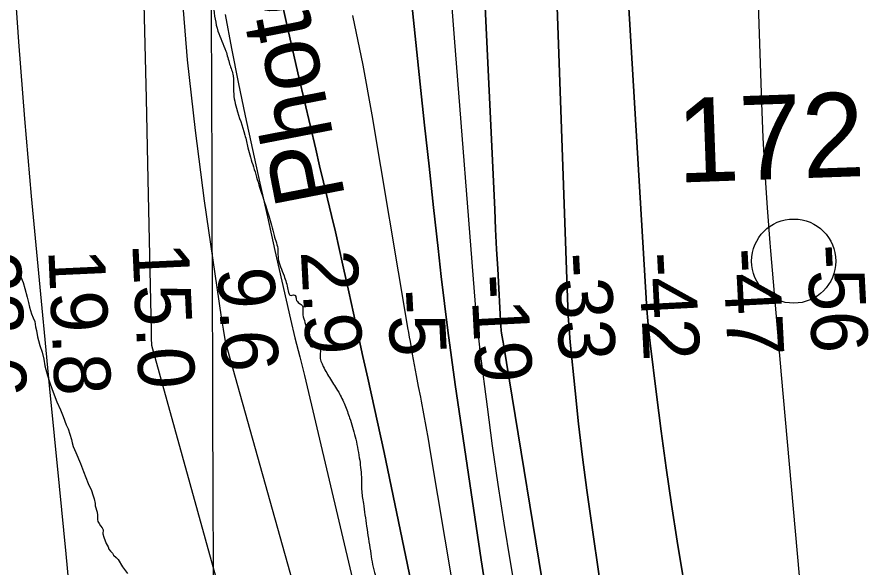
# Model space of a CAD drawing. Extents: x 3392644 to 3430565, y 576657 to 602123.
# Drawn here: x 3401788 to 3402811, y 590281 to 590935 of the extents above; entities that cross this region are included whole.
import ezdxf

# ---------------------------------------------------------------- set-up
doc = ezdxf.new("R2010")
doc.units = 0
for name, color, linetype in [('V-GRID-MAJR', 7, 'Continuous'), ('V-RIVR-EDGE', 7, 'Continuous'), ('V-RIVR-IDEN', 7, 'Continuous'), ('V-RIVR-MILE', 7, 'Continuous'), ('V-RIVR-RANG', 7, 'Continuous'), ('V-SITE-VEGE', 7, 'Continuous'), ('V-TOPO-DPTH', 7, 'Continuous'), ('V-TOPO-MAJR', 7, 'Continuous'), ('V-TOPO-MINR', 7, 'Continuous'), ('V-TOPO-WATR', 7, 'Continuous')]:
    doc.layers.add(name, color=color, linetype=linetype)

msp = doc.modelspace()

# ---------------------------------------------------------------- linework, layer by layer
at = {"layer": 'V-GRID-MAJR'}
msp.add_spline([(3402048.6720000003, 582063.4890000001), (3402028.4020000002, 588122.6730000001), (3402008.125, 594183.791), (3401987.849, 600244.93), (3401987.843, 600246.845)], degree=3, dxfattribs=at)
at = {"layer": 'V-RIVR-EDGE'}
for points in [[(3401987.9213314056, 591815.3849305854), (3401986.374240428, 591794.2696732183), (3401984.9403506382, 591784.4067082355), (3401983.8640619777, 591776.657111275), (3401978.9012120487, 591764.6886201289), (3401977.1132064, 591754.1217800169), (3401973.567691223, 591745.3211626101), (3401971.4360255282, 591738.2789260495), (3401969.6454059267, 591726.6549662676), (3401969.2668931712, 591716.0846408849), (3401969.2590513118, 591712.9132818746), (3401968.1827626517, 591705.1636849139), (3401965.688267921, 591693.8938409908), (3401962.838786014, 591681.5677487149), (3401961.7755671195, 591679.1037501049), (3401961.420579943, 591678.0475017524), (3401960.3608463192, 591676.9929960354), (3401957.895105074, 591677.351468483), (3401951.2113409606, 591681.9488754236), (3401944.5240915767, 591685.1367894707), (3401941.7051057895, 591685.1437600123), (3401942.052251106, 591683.0286493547), (3401946.620033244, 591677.7317238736), (3401950.8371847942, 591673.1404161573), (3401957.5113644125, 591664.6669037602), (3401962.0843744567, 591661.4842176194), (3401967.720603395, 591660.7655300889), (3401970.1819880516, 591658.6451915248), (3401967.3473185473, 591652.309444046), (3401963.8201010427, 591650.9086643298), (3401963.465113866, 591649.8524159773), (3401963.457272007, 591646.681056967), (3401964.845853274, 591638.2206143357), (3401962.369656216, 591634.3506081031), (3401959.531501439, 591626.6053677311), (3401959.5245308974, 591623.7863819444), (3401959.849893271, 591612.8619407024), (3401959.83508087, 591606.8715959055), (3401960.503231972, 591592.0701778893), (3401959.085897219, 591588.9023041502), (3401954.8548045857, 591587.8556402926), (3401949.5665922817, 591586.8115903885), (3401948.5025020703, 591583.995218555), (3401948.4842043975, 591576.5953808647), (3401949.8928259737, 591576.2395223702), (3401955.530797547, 591576.2255812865), (3401957.2883070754, 591574.4593585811), (3401957.27872258, 591570.5832531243), (3401962.5102992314, 591548.7230435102), (3401966.3280264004, 591525.1044530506), (3401969.443621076, 591502.5447248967), (3401975.3869147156, 591483.5017584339), (3401978.862724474, 591464.112517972), (3401980.895059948, 591430.9842070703), (3401982.5889632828, 591403.4947390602), (3401980.7844025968, 591386.2328077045), (3401978.650122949, 591378.1334514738), (3401977.190093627, 591357.6992897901), (3401976.752331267, 591323.1675852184), (3401976.330252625, 591294.9785986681), (3401975.6089511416, 591288.2852500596), (3401977.3481629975, 591279.1191896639), (3401981.890676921, 591263.6034407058), (3401986.4410327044, 591251.2590507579), (3401992.0302104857, 591231.5122091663), (3401995.162360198, 591215.6475722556), (3402000.3695399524, 591183.9209123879), (3402003.4642230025, 591152.904226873), (3402003.0177474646, 591114.8487900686), (3402003.616193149, 591071.8575141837), (3402003.1975997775, 591045.0780205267), (3402005.2621740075, 591024.987518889), (3402008.735369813, 591004.5411587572), (3402015.3502998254, 590972.1062671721), (3402020.9281504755, 590947.7785736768), (3402026.4946739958, 590918.8700282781), (3402035.9503727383, 590895.2374967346), (3402040.4928866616, 590879.7217477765), (3402044.68738395, 590865.968736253), (3402045.0005478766, 590850.1110698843), (3402048.467644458, 590827.198097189), (3402058.6080493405, 590795.4592388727), (3402062.094314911, 590780.2984770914), (3402068.73364182, 590757.7300357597), (3402076.0733585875, 590733.3979856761), (3402090.056758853, 590688.2593603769), (3402093.19849306, 590676.2708289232), (3402097.73490776, 590658.2884674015), (3402098.0637554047, 590648.7735190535), (3402100.858344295, 590638.9000982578), (3402105.0606834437, 590628.3184457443)], [(3402105.0606834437, 590628.3184457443), (3402109.601454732, 590612.09795034), (3402110.2974880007, 590608.5724754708), (3402112.403014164, 590605.0435153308), (3402117.337110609, 590605.383690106), (3402118.3924876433, 590604.6763297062), (3402119.439151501, 590600.4452370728), (3402123.3030585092, 590595.502427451), (3402126.819820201, 590592.6747284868), (3402127.1582523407, 590587.0358855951), (3402131.3405511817, 590568.3496489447), (3402134.468344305, 590550.7231459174), (3402136.9192731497, 590544.3743286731), (3402142.908746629, 590544.0071430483), (3402147.13286872, 590542.2348211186), (3402147.8167035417, 590533.7761211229), (3402151.659698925, 590520.3763541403), (3402160.0800609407, 590505.555767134), (3402169.908173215, 590490.0269484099)], [(3402169.908173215, 590490.0269484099), (3402177.270544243, 590474.8566021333), (3402182.8701778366, 590459.3382392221), (3402189.5103760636, 590437.122171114), (3402194.3817376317, 590412.0914738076), (3402196.7917145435, 590389.1811150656), (3402197.107492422, 590374.3805683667), (3402199.180779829, 590357.8137989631), (3402202.9897938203, 590330.6714762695), (3402207.4983263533, 590301.4131716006), (3402212.367945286, 590275.6777278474), (3402219.3692299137, 590256.9845206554), (3402224.268473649, 590243.2297664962), (3402225.6457277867, 590230.1884719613), (3402225.599547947, 590211.5126911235)]]:
    msp.add_spline(points, degree=3, dxfattribs=at)
at = {"layer": 'V-RIVR-MILE'}
msp.add_circle((3402710.0330000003, 590645.697), 50.00000000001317, dxfattribs=at)
at = {"layer": 'V-SITE-VEGE'}
for points in [[(3401787.631, 590639.961), (3401792.1380000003, 590627.808), (3401795.307, 590620.3250000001), (3401797.549, 590613.317), (3401800.218, 590603.0480000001), (3401801.535, 590596.517), (3401802.864, 590590.916), (3401805.096, 590582.978), (3401807.365, 590578.2980000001), (3401809.178, 590574.087), (3401810.0300000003, 590567.562), (3401811.375, 590563.358), (3401812.217, 590555.901), (3401813.556, 590551.232), (3401815.35, 590545.626), (3401818.048, 590537.682), (3401819.807, 590529.283), (3401821.107, 590521.357), (3401824.224, 590509.686), (3401826.463, 590502.213), (3401829.613, 590493.333), (3401835.482, 590478.37), (3401839.56, 590469.015), (3401842.722, 590461.064), (3401846.326, 590451.248), (3401848.596, 590446.568), (3401852.632, 590433.955), (3401853.5130000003, 590429.756), (3401854.858, 590425.552), (3401858.0330000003, 590418.533), (3401863.46, 590405.438), (3401867.0640000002, 590395.622), (3401872.4790000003, 590381.596), (3401876.5670000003, 590373.17), (3401877.9, 590368.034), (3401879.707, 590363.36), (3401881.036, 590357.759), (3401881.001, 590354.968), (3401883.24, 590347.4940000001), (3401883.659, 590343.767), (3401883.598, 590338.647), (3401884.034, 590336.316), (3401885.4020000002, 590333.974), (3401887.231, 590331.16), (3401889.0640000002, 590328.811), (3401890.432, 590326.468), (3401889.912, 590321.819), (3401891.253, 590317.6140000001), (3401893.9590000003, 590310.137), (3401896.24, 590306.387), (3401897.137, 590303.583), (3401898.97, 590301.234)], [(3401898.97, 590301.234), (3401901.268, 590298.879), (3401902.636, 590296.536), (3401905.86, 590293.706), (3401908.16, 590291.351), (3401913.171, 590282.452), (3401919.125, 590274.4670000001)]]:
    msp.add_lwpolyline(points, dxfattribs=at)
at = {"layer": 'V-TOPO-DPTH'}
for points in [[(3402353.3290655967, 590199.9457083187), (3402339.159093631, 590290.6627414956), (3402325.4791854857, 590381.4583590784), (3402308.2305314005, 590499.1779455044), (3402303.7065030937, 590531.1938928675), (3402299.401020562, 590563.2380676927), (3402295.4233566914, 590595.3245837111), (3402291.6642385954, 590627.4393271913), (3402287.936642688, 590660.7589617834), (3402282.5295418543, 590709.5603148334), (3402277.191595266, 590758.3691565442), (3402271.9573800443, 590807.189231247), (3402266.7923190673, 590856.0167946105), (3402219.383289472, 591308.7931476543)], [(3402353.3290655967, 590199.9457083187), (3402339.159093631, 590290.6627414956), (3402325.4791854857, 590381.4583590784), (3402308.2305314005, 590499.1779455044), (3402303.7065030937, 590531.1938928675), (3402299.401020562, 590563.2380676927), (3402295.4233566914, 590595.3245837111), (3402291.6642385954, 590627.4393271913), (3402287.936642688, 590660.7589617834), (3402282.5295418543, 590709.5603148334), (3402277.191595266, 590758.3691565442), (3402271.9573800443, 590807.189231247), (3402266.7923190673, 590856.0167946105), (3402219.383289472, 591308.7931476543)], [(3402328.8555681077, 591263.8165721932), (3402355.1042787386, 590706.9785494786), (3402356.2409415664, 590683.5243978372), (3402357.418917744, 590660.072376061), (3402358.658863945, 590636.6235490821), (3402359.9401234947, 590613.176851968), (3402362.51507586, 590567.1717141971), (3402362.54368278, 590566.7295099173), (3402362.6653002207, 590565.4059425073), (3402362.912461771, 590563.2440096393), (3402363.3030222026, 590560.2074731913), (3402364.0102189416, 590555.8374731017), (3402364.7517568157, 590551.4721740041), (3402365.1158288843, 590549.2884000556), (3402365.47655252, 590547.1040639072), (3402421.4570020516, 590205.6760027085)], [(3402421.4570020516, 590205.6760027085), (3402365.47655252, 590547.1040639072), (3402365.1158288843, 590549.2884000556), (3402364.7517568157, 590551.4721740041), (3402364.0102189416, 590555.8374731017), (3402363.3030222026, 590560.2074731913), (3402362.912461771, 590563.2440096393), (3402362.6653002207, 590565.4059425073), (3402362.54368278, 590566.7295099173), (3402362.51507586, 590567.1717141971), (3402359.9401234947, 590613.176851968), (3402358.658863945, 590636.6235490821), (3402357.418917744, 590660.072376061), (3402356.2409415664, 590683.5243978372), (3402355.1042787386, 590706.9785494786), (3402328.8555681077, 591263.8165721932)], [(3402419.2592754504, 591226.801684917), (3402441.8902075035, 590590.9287009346), (3402442.3584527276, 590580.5782815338), (3402442.9594238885, 590570.2368586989), (3402443.759483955, 590559.9089307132), (3402444.6922699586, 590549.5899992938), (3402450.503854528, 590491.5416000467), (3402454.7096263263, 590452.2381662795), (3402459.271995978, 590412.9786390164), (3402464.369262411, 590373.784971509), (3402469.823126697, 590334.6352105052), (3402489.9257230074, 590197.1958148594)], [(3402489.9257230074, 590197.1958148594), (3402469.823126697, 590334.6352105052), (3402464.369262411, 590373.784971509), (3402459.271995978, 590412.9786390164), (3402454.7096263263, 590452.2381662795), (3402450.503854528, 590491.5416000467), (3402444.6922699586, 590549.5899992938), (3402443.759483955, 590559.9089307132), (3402442.9594238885, 590570.2368586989), (3402442.3584527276, 590580.5782815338), (3402441.8902075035, 590590.9287009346), (3402419.2592754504, 591226.801684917)], [(3402507.9374777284, 591053.0573189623), (3402534.915903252, 590601.4970560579), (3402535.8334838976, 590588.1657816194), (3402536.911551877, 590574.8489618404), (3402538.230350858, 590561.5538240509), (3402539.7096371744, 590548.2731409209), (3402547.0492716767, 590487.3910313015), (3402552.597272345, 590443.7197401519), (3402558.516386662, 590400.1012258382), (3402564.9921714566, 590356.5618767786), (3402571.839069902, 590313.075304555), (3402584.837502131, 590233.8169605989)], [(3402507.9374777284, 591053.0573189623), (3402534.915903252, 590601.4970560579), (3402535.8334838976, 590588.1657816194), (3402536.911551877, 590574.8489618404), (3402538.230350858, 590561.5538240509), (3402539.7096371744, 590548.2731409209), (3402547.0492716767, 590487.3910313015), (3402552.597272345, 590443.7197401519), (3402558.516386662, 590400.1012258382), (3402564.9921714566, 590356.5618767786), (3402571.839069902, 590313.075304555), (3402584.837502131, 590233.8169605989)], [(3402094.4613117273, 590989.3579844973), (3402108.172264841, 590926.7030621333), (3402122.4636430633, 590864.1709425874), (3402142.6516267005, 590778.5766909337), (3402147.2949938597, 590758.9363289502), (3402151.9523181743, 590739.2992850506), (3402156.630578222, 590719.6672182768), (3402161.3227954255, 590700.0384695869), (3402165.9591106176, 590680.3970933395), (3402170.5069419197, 590660.7355643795), (3402174.922047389, 590641.0438063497), (3402179.24866897, 590621.3318956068), (3402181.828992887, 590609.3837472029), (3402187.4004638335, 590583.6872539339), (3402193.000011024, 590557.9969043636), (3402198.641672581, 590532.3157703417), (3402204.311410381, 590506.6407800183), (3402223.9148138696, 590418.212562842), (3402300.667923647, 590048.5866816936)], [(3402300.667923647, 590048.5866816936), (3402223.9148138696, 590418.212562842), (3402204.311410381, 590506.6407800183), (3402198.641672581, 590532.3157703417), (3402193.000011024, 590557.9969043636), (3402187.4004638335, 590583.6872539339), (3402181.828992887, 590609.3837472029), (3402179.24866897, 590621.3318956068), (3402174.922047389, 590641.0438063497), (3402170.5069419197, 590660.7355643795), (3402165.9591106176, 590680.3970933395), (3402161.3227954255, 590700.0384695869), (3402156.630578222, 590719.6672182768), (3402151.9523181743, 590739.2992850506), (3402147.2949938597, 590758.9363289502), (3402142.6516267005, 590778.5766909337), (3402122.4636430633, 590864.1709425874), (3402108.172264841, 590926.7030621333), (3402094.4613117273, 590989.3579844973)], [(3401983.2324119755, 590968.6679456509), (3401990.1753502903, 590884.6576055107), (3401999.4954309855, 590800.8776691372), (3402010.400273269, 590717.2513352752), (3402030.3982368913, 590579.1808770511), (3402032.694975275, 590564.7437197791), (3402035.258030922, 590550.3578455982), (3402268.230022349, 589718.4169068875), (3402274.4846897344, 589684.2706644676), (3402439.6848734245, 589005.6338973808), (3402443.7939876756, 588979.9680700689), (3402446.98534152, 588954.2132787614), (3402448.800054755, 588928.3250414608), (3402356.816492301, 588119.580552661)]]:
    msp.add_lwpolyline(points, dxfattribs=at)
at = {"layer": 'V-TOPO-MAJR'}
msp.add_lwpolyline([(3402811.0013850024, 589574.9739549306), (3402798.9128169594, 589636.3194171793), (3402786.4733180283, 589698.572373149), (3402780.689725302, 589728.8028692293), (3402775.2373893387, 589759.0902010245), (3402770.281938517, 589789.4627863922), (3402765.6577444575, 589819.8922074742), (3402758.7759854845, 589867.8174313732), (3402751.3999859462, 589922.3033309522), (3402744.610935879, 589976.8574738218), (3402738.702310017, 590031.513981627), (3402733.3806336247, 590086.2387327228), (3402695.571573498, 590510.5253860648), (3402692.3134362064, 590547.3791651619), (3402689.089671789, 590584.2359265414), (3402685.917466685, 590621.0971613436), (3402682.7796344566, 590657.961378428), (3402681.988514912, 590667.333255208), (3402678.794508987, 590708.9042059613), (3402676.0184252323, 590750.499888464), (3402673.869224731, 590792.132668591), (3402672.1379464, 590833.7901804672), (3402658.1828608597, 591244.0353686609)], dxfattribs=at)
at = {"layer": 'V-TOPO-MINR'}
for points in [[(3402219.383289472, 591308.7931476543), (3402266.7923190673, 590856.0167946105), (3402271.9573800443, 590807.189231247), (3402277.191595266, 590758.3691565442), (3402282.5295418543, 590709.5603148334), (3402287.936642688, 590660.7589617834), (3402291.6642385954, 590627.4393271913), (3402295.4233566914, 590595.3245837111), (3402299.401020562, 590563.2380676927), (3402303.7065030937, 590531.1938928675), (3402308.2305314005, 590499.1779455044), (3402325.4791854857, 590381.4583590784), (3402339.159093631, 590290.6627414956), (3402353.3290655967, 590199.9457083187)], [(3402328.8555681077, 591263.8165721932), (3402355.1042787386, 590706.9785494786), (3402356.2409415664, 590683.5243978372), (3402357.418917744, 590660.072376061), (3402358.658863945, 590636.6235490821), (3402359.9401234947, 590613.176851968), (3402362.51507586, 590567.1717141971), (3402362.54368278, 590566.7295099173), (3402362.6653002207, 590565.4059425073), (3402362.912461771, 590563.2440096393), (3402363.3030222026, 590560.2074731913), (3402364.0102189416, 590555.8374731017), (3402364.7517568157, 590551.4721740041), (3402365.1158288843, 590549.2884000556), (3402365.47655252, 590547.1040639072), (3402421.4570020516, 590205.6760027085)], [(3402419.2592754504, 591226.801684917), (3402441.8902075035, 590590.9287009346), (3402442.3584527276, 590580.5782815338), (3402442.9594238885, 590570.2368586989), (3402443.759483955, 590559.9089307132), (3402444.6922699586, 590549.5899992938), (3402450.503854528, 590491.5416000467), (3402454.7096263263, 590452.2381662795), (3402459.271995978, 590412.9786390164), (3402464.369262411, 590373.784971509), (3402469.823126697, 590334.6352105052), (3402489.9257230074, 590197.1958148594)], [(3402584.837502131, 590233.8169605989), (3402571.839069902, 590313.075304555), (3402564.9921714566, 590356.5618767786), (3402558.516386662, 590400.1012258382), (3402552.597272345, 590443.7197401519), (3402547.0492716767, 590487.3910313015), (3402539.7096371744, 590548.2731409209), (3402538.230350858, 590561.5538240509), (3402536.911551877, 590574.8489618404), (3402535.8334838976, 590588.1657816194), (3402534.915903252, 590601.4970560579), (3402507.9374777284, 591053.0573189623)], [(3401936.680185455, 591031.3200367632), (3401939.044525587, 590935.1207899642), (3401941.2601198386, 590838.9180024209), (3401943.3765501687, 590742.7128543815), (3401947.2046294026, 590562.3615172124), (3401947.432742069, 590554.1671924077), (3401947.733002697, 590545.975989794), (3402173.1077528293, 589731.3317674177), (3402178.1472349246, 589711.3207787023), (3402400.0589522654, 589018.2294907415), (3402401.8446181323, 589011.4077743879), (3402403.357249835, 589004.5056818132), (3402410.2584788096, 588967.715218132), (3402411.514057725, 588959.8725564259), (3402412.4892003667, 588952.0027114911), (3402413.043688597, 588944.0920917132), (3402320.7812215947, 588156.1759327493)], [(3401783.3508998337, 590997.885167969), (3401789.683309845, 590906.1667832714), (3401797.028580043, 590814.5239520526), (3401805.0490903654, 590722.9314898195), (3401818.20864063, 590581.6383566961), (3401820.178450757, 590560.7324256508), (3401822.1782628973, 590539.8293975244), (3401824.223078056, 590518.9307237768), (3401826.297895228, 590498.0349529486), (3401838.2976932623, 590378.4923784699), (3401846.1330074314, 590297.8040644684), (3401853.619150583, 590217.0845093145), (3401860.58153721, 590136.3180924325), (3401867.1947528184, 590055.520434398), (3401892.587545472, 589732.3945569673), (3401894.3767023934, 589711.1015344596), (3401896.3191168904, 589689.8233379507), (3402014.2872907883, 588943.2527003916)], [(3402301.853980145, 590977.8037209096), (3402307.062503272, 590911.0643158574), (3402331.998971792, 590594.0090889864), (3402333.24695874, 590579.4662834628), (3402334.6326918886, 590564.9376058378), (3402336.225044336, 590550.4301200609), (3402337.955142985, 590535.9367621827), (3402345.9868266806, 590472.4932565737), (3402352.1481145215, 590426.3354205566), (3402358.725211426, 590380.2397898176), (3402365.9260219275, 590334.2374669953), (3402373.5426414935, 590288.2973494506), (3402382.7195201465, 590235.1785017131)], [(3401983.2324119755, 590968.6679456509), (3401990.1753502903, 590884.6576055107), (3401999.4954309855, 590800.8776691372), (3402010.400273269, 590717.2513352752), (3402030.3982368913, 590579.1808770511), (3402032.694975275, 590564.7437197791), (3402035.258030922, 590550.3578455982), (3402268.230022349, 589718.4169068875), (3402274.4846897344, 589684.2706644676), (3402439.6848734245, 589005.6338973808), (3402443.7939876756, 588979.9680700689), (3402446.98534152, 588954.2132787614), (3402448.800054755, 588928.3250414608), (3402356.816492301, 588119.580552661)], [(3402035.2523009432, 590938.4310933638), (3402042.638547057, 590898.2338251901), (3402050.6078128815, 590858.1480695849), (3402058.9657585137, 590818.1366556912), (3402067.662495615, 590778.1914244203), (3402076.422084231, 590738.260058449), (3402085.27595012, 590698.3494904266), (3402094.1926675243, 590658.452787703), (3402107.4830322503, 590599.314902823), (3402112.667992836, 590576.8350316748), (3402118.0209276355, 590554.3962314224), (3402123.625823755, 590532.0190375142), (3402129.398694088, 590509.6829145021), (3402314.967871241, 589722.0039368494), (3402317.1774762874, 589710.9680229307), (3402319.4037851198, 589699.9354337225), (3402326.2408264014, 589666.2513266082), (3402329.6393938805, 589650.1656333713), (3402333.207985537, 589634.1191751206), (3402337.031613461, 589618.1315693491)], [(3402186.2509795, 590937.2909226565), (3402198.410272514, 590878.5086845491), (3402209.293247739, 590819.440609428), (3402250.751882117, 590571.7634428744), (3402251.6738545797, 590566.334710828), (3402252.612998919, 590560.9089931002), (3402253.5779010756, 590555.4877968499), (3402254.5599751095, 590550.0696149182), (3402257.27683744, 590535.2806722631), (3402259.6417779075, 590522.472438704), (3402262.022125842, 590509.66708358), (3402264.4255849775, 590496.8660461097), (3402266.84445158, 590484.0678870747), (3402267.716787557, 590479.4751003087), (3402270.535836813, 590464.3741921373), (3402273.29150384, 590449.2619322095), (3402275.952097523, 590434.1326446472), (3402278.549308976, 590418.9920053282), (3402322.1771919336, 590159.7720269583)]]:
    msp.add_lwpolyline(points, dxfattribs=at)
at = {"layer": 'V-TOPO-WATR'}
msp.add_lwpolyline([(3402094.4613117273, 590989.3579844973), (3402108.172264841, 590926.7030621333), (3402122.4636430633, 590864.1709425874), (3402142.6516267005, 590778.5766909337), (3402147.2949938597, 590758.9363289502), (3402151.9523181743, 590739.2992850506), (3402156.630578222, 590719.6672182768), (3402161.3227954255, 590700.0384695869), (3402165.9591106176, 590680.3970933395), (3402170.5069419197, 590660.7355643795), (3402174.922047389, 590641.0438063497), (3402179.24866897, 590621.3318956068), (3402181.828992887, 590609.3837472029), (3402187.4004638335, 590583.6872539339), (3402193.000011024, 590557.9969043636), (3402198.641672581, 590532.3157703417), (3402204.311410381, 590506.6407800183), (3402223.9148138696, 590418.212562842), (3402300.667923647, 590048.5866816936)], dxfattribs=at)

# ---------------------------------------------------------------- texts
at = {"layer": 'V-RIVR-IDEN'}
for s, height, rotation, p in [('Photos', 83, 101.0107529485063, (3402178.038564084, 590721.1296090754)), ('172', 100.00000199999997, 2.0338777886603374, (3402572.611, 590738.912))]:
    msp.add_text(s, height=height, rotation=rotation, dxfattribs=at).set_placement(p)
at = {"layer": 'V-RIVR-RANG'}
for s, height, rotation, p in [('15.0', 67, 272.65832571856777, (3401924.8281457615, 590666.6847763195)), ('-47', 67.00000000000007, 272.94561111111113, (3402625.4768474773, 590660.1618240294)), ('-56', 67.00000000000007, 272.94561111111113, (3402725.3849576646, 590664.5269620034)), ('22.6', 67, 272.65832571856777, (3401725.1170820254, 590655.8467936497)), ('19.8', 67, 272.65832571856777, (3401825.0827204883, 590658.8943239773)), ('2.9', 67.00000000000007, 272.94561111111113, (3402124.9643297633, 590657.3031670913)), ('-33', 67.00000000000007, 272.94561111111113, (3402425.499965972, 590654.5927202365)), ('-42', 67.00000000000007, 272.94561111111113, (3402525.596847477, 590655.2698240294)), ('9.6', 67, 272.65832571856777, (3402026.2995743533, 590637.3223395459)), ('-19', 67.00000000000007, 272.94561111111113, (3402326.6908184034, 590628.8896702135)), ('-5', 67.00000000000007, 272.94561111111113, (3402227.5011282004, 590610.5626885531))]:
    msp.add_text(s, height=height, rotation=rotation, dxfattribs=at).set_placement(p)

doc.saveas('drawing.dxf')
